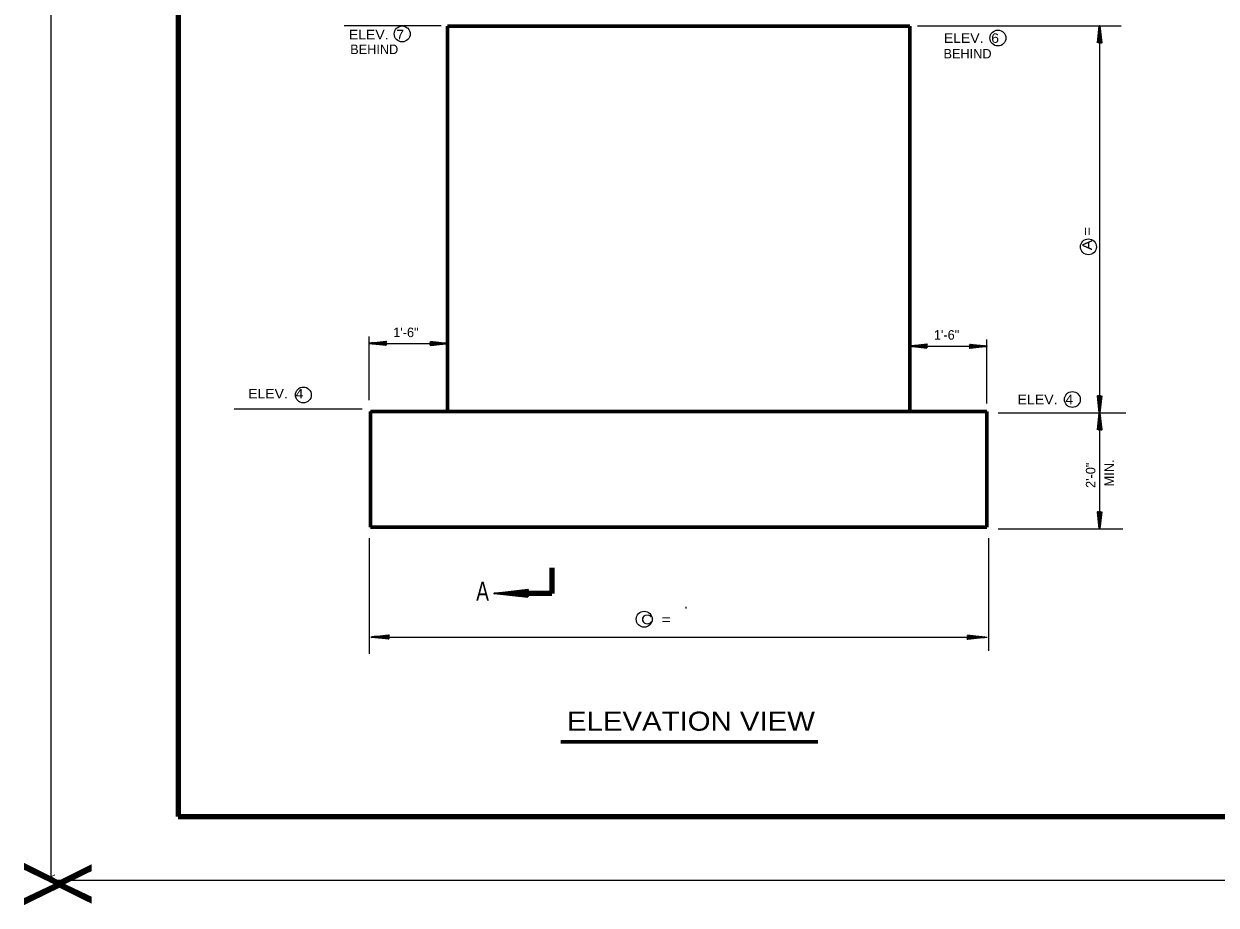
# Model space of a CAD drawing. Extents: x 1.6 to 19.9, y 2.8 to 9.5.
# Drawn here: x 16.233 to 17.696, y 7.258 to 8.339 of the extents above; entities that cross this region are included whole.
import ezdxf
from ezdxf.enums import TextEntityAlignment as Align

# ---------------------------------------------------------------- set-up
doc = ezdxf.new("R2010")
doc.units = 0
doc.header["$LTSCALE"] = 0.0047
doc.layers.add('1', color=7, linetype='Continuous', lineweight=35)
doc.layers.add('5', color=7, linetype='Continuous', lineweight=13)

msp = doc.modelspace()

# ---------------------------------------------------------------- linework, layer by layer
at = {"layer": '1', "lineweight": 25}
for p, q in [((16.26675, 9.5485), (16.26675, 7.2855)), ((16.6265, 8.33725), (16.74525, 8.33725)), ((17.329917, 8.336833), (17.5795, 8.336833)), ((17.55325, 8.3325), (17.55325, 7.719833)), ((16.65725, 7.877667), (16.65725, 7.95575)), ((16.657417, 7.94725), (16.750417, 7.94725)), ((17.321417, 7.943833), (17.414417, 7.943833)), ((17.414917, 7.87375), (17.414917, 7.951917)), ((16.491667, 7.866917), (16.648667, 7.866917)), ((17.428583, 7.862), (17.5855, 7.862)), ((17.428583, 7.719833), (17.581667, 7.719833)), ((16.65725, 7.70825), (16.65725, 7.5665)), ((17.416833, 7.70825), (17.416833, 7.570083)), ((16.659167, 7.587), (17.027, 7.587)), ((17.027, 7.587), (17.41525, 7.587)), ((17.02725, 7.587333), (17.027333, 7.587333)), ((16.26675, 7.288833), (19.894917, 7.288833))]:
    msp.add_line(p, q, dxfattribs=at)
at = {"layer": '1', "lineweight": 60}
for p, q in [((17.320417, 8.336333), (17.320417, 7.86375)), ((16.658667, 7.722), (16.658667, 7.86375)), ((17.320417, 7.86375), (17.414917, 7.86375)), ((17.414917, 7.86375), (17.414917, 7.722)), ((17.045167, 7.722), (16.658667, 7.722)), ((17.414917, 7.722), (17.045167, 7.722)), ((17.207583, 7.4585), (16.892167, 7.4585))]:
    msp.add_line(p, q, dxfattribs=at)
at = {"layer": '1'}
for p, q in [((17.551167, 8.316583), (17.55275, 8.332)), ((17.551167, 8.3165), (17.552917, 8.332)), ((17.551167, 8.3165), (17.552917, 8.332)), ((17.551417, 8.3165), (17.553, 8.331917)), ((17.5515, 8.3165), (17.55325, 8.331917)), ((17.554417, 8.316417), (17.552917, 8.33075)), ((17.553083, 8.316083), (17.553083, 8.336833)), ((17.554667, 8.3165), (17.553083, 8.330917)), ((17.554917, 8.3165), (17.553333, 8.331)), ((17.555167, 8.316583), (17.5535, 8.331)), ((16.677917, 7.94725), (16.65725, 7.94725)), ((16.677417, 7.94525), (16.662083, 7.947)), ((16.677417, 7.945333), (16.662083, 7.947)), ((16.677417, 7.945417), (16.662083, 7.947)), ((16.677583, 7.94575), (16.662167, 7.947333)), ((16.677417, 7.9455), (16.662167, 7.94725)), ((16.677417, 7.94925), (16.663083, 7.947667)), ((16.677417, 7.949083), (16.663083, 7.9475)), ((16.677583, 7.948833), (16.663167, 7.94725)), ((16.677583, 7.948583), (16.663167, 7.947)), ((16.732167, 7.94725), (16.753, 7.94725)), ((16.732417, 7.946), (16.747, 7.9475)), ((16.732583, 7.94925), (16.748083, 7.9475)), ((16.732583, 7.949167), (16.748083, 7.9475)), ((16.732583, 7.949083), (16.748083, 7.947333)), ((16.732583, 7.948833), (16.748083, 7.947167)), ((16.732583, 7.94575), (16.747, 7.94725)), ((16.732583, 7.9455), (16.747083, 7.947)), ((16.732667, 7.949333), (16.748083, 7.947583)), ((16.732667, 7.94525), (16.747083, 7.946917)), ((17.341167, 7.943833), (17.3205, 7.943833)), ((17.340833, 7.94225), (17.325417, 7.943917)), ((17.34075, 7.942), (17.325417, 7.94375)), ((17.34075, 7.941917), (17.325417, 7.943583)), ((17.34075, 7.942), (17.325417, 7.943583)), ((17.34075, 7.941833), (17.325417, 7.9435)), ((17.34075, 7.94575), (17.326417, 7.94425)), ((17.34075, 7.945667), (17.326417, 7.944083)), ((17.340833, 7.945417), (17.326417, 7.943833)), ((17.340833, 7.945167), (17.326417, 7.943583)), ((17.394, 7.943833), (17.414917, 7.943833)), ((17.394333, 7.9425), (17.408917, 7.944083)), ((17.394417, 7.94575), (17.409917, 7.944083)), ((17.394417, 7.94575), (17.409917, 7.944)), ((17.394417, 7.945667), (17.409917, 7.943917)), ((17.394417, 7.945417), (17.409917, 7.94375)), ((17.394417, 7.94225), (17.408917, 7.943833)), ((17.394417, 7.942), (17.408917, 7.943583)), ((17.3945, 7.945917), (17.409917, 7.944167)), ((17.3945, 7.941833), (17.408917, 7.9435)), ((17.551333, 7.8825), (17.552917, 7.868083)), ((17.5515, 7.8825), (17.553083, 7.868083)), ((17.55175, 7.8825), (17.553333, 7.868167)), ((17.552, 7.8825), (17.553667, 7.86825)), ((17.55325, 7.882917), (17.55325, 7.86225)), ((17.554917, 7.8825), (17.55325, 7.867167)), ((17.555083, 7.8825), (17.553333, 7.867167)), ((17.555167, 7.8825), (17.553583, 7.867)), ((17.555417, 7.8825), (17.553667, 7.867)), ((17.55525, 7.8825), (17.553667, 7.867)), ((17.551333, 7.841833), (17.552917, 7.85725)), ((17.551333, 7.84175), (17.553, 7.85725)), ((17.551417, 7.84175), (17.553083, 7.85725)), ((17.5515, 7.84175), (17.553167, 7.857167)), ((17.551667, 7.84175), (17.553417, 7.857167)), ((17.554583, 7.841667), (17.553, 7.856)), ((17.554833, 7.84175), (17.55325, 7.856083)), ((17.555083, 7.84175), (17.5535, 7.85625)), ((17.55525, 7.841833), (17.553667, 7.85625)), ((17.551333, 7.74025), (17.552917, 7.72575)), ((17.5515, 7.74025), (17.553083, 7.72575)), ((17.55175, 7.74025), (17.553333, 7.725917)), ((17.552, 7.74025), (17.553667, 7.726)), ((17.55325, 7.740667), (17.55325, 7.72)), ((17.554917, 7.74025), (17.55325, 7.724833)), ((17.555083, 7.74025), (17.553333, 7.724833)), ((17.555167, 7.74025), (17.553583, 7.72475)), ((17.555417, 7.74025), (17.553667, 7.72475)), ((17.55525, 7.74025), (17.553667, 7.72475)), ((16.851917, 7.640667), (16.8105, 7.640667)), ((16.851083, 7.636917), (16.820167, 7.640167)), ((16.851083, 7.63675), (16.820167, 7.640083)), ((16.851, 7.636583), (16.820167, 7.64)), ((16.851167, 7.6375), (16.820417, 7.64075)), ((16.851083, 7.637), (16.820417, 7.6405)), ((16.851, 7.6445), (16.82225, 7.641417)), ((16.851083, 7.644167), (16.822333, 7.641)), ((16.851167, 7.64375), (16.822417, 7.640583)), ((16.851167, 7.64325), (16.822417, 7.640083)), ((16.681333, 7.587), (16.660583, 7.587)), ((16.680833, 7.585083), (16.665417, 7.586833)), ((16.680833, 7.585167), (16.665417, 7.586833)), ((16.680833, 7.585), (16.665417, 7.58675)), ((16.680917, 7.5855), (16.6655, 7.587167)), ((16.680833, 7.58525), (16.6655, 7.587)), ((16.680833, 7.589), (16.666417, 7.5875)), ((16.680833, 7.588833), (16.666417, 7.58725)), ((16.680917, 7.588583), (16.6665, 7.587)), ((16.680917, 7.588417), (16.6665, 7.586833)), ((17.391083, 7.587), (17.411917, 7.587)), ((17.391417, 7.588917), (17.407, 7.58725)), ((17.391417, 7.588833), (17.407, 7.587167)), ((17.391417, 7.58875), (17.407, 7.587)), ((17.391417, 7.5885), (17.407, 7.586833)), ((17.391417, 7.585667), (17.405917, 7.58725)), ((17.391417, 7.585417), (17.405917, 7.587)), ((17.391417, 7.585167), (17.406, 7.58675)), ((17.3915, 7.589), (17.407, 7.58725)), ((17.3915, 7.585), (17.406, 7.586583))]:
    msp.add_line(p, q, dxfattribs=at)
at = {"layer": '1', "lineweight": 90}
for p, q in [((16.881333, 7.672), (16.881333, 7.640583)), ((16.881333, 7.640583), (16.849667, 7.640583))]:
    msp.add_line(p, q, dxfattribs=at)
at = {"layer": '1', "lineweight": 13}
msp.add_line((17.045417, 7.624167), (17.045417, 7.622167), dxfattribs=at)
at = {"layer": '1', "lineweight": 106}
msp.add_line((16.423, 7.367), (19.823, 7.367), dxfattribs=at)
msp.add_lwpolyline([(19.823, 7.367), (19.823, 9.467), (16.423, 9.467), (16.423, 7.367)], dxfattribs=at)
at = {"layer": '1', "lineweight": 60}
for points in [[(16.658667, 7.86375), (16.753167, 7.86375), (16.753167, 8.336417)], [(16.753167, 8.336417), (17.052167, 8.336417), (17.320417, 8.336417)], [(16.753167, 7.86375), (17.044917, 7.86375), (17.320417, 7.86375)]]:
    msp.add_lwpolyline(points, dxfattribs=at)
at = {"layer": '1'}
for points in [[(17.550833, 8.316083), (17.553083, 8.336833), (17.555417, 8.316083), (17.553083, 8.31725)], [(16.677917, 7.945), (16.65725, 7.94725), (16.677917, 7.949667), (16.676833, 7.94725)], [(16.732167, 7.9495), (16.753, 7.94725), (16.732167, 7.945), (16.73325, 7.94725)], [(17.341167, 7.941583), (17.3205, 7.943833), (17.341167, 7.94625), (17.340167, 7.943833)], [(17.394, 7.946083), (17.414917, 7.943833), (17.394, 7.9415), (17.395167, 7.943833)], [(17.555583, 7.882917), (17.55325, 7.86225), (17.551, 7.882917), (17.553333, 7.881833)], [(17.553667, 7.8815), (17.553667, 7.87225), (17.553417, 7.872333), (17.553667, 7.874083)], [(17.551, 7.841333), (17.55325, 7.862), (17.555583, 7.841333), (17.55325, 7.8425)], [(17.555583, 7.740667), (17.55325, 7.72), (17.551, 7.740667), (17.553333, 7.7395)], [(17.553667, 7.73925), (17.553667, 7.73), (17.553417, 7.730083), (17.553667, 7.731833)], [(16.851917, 7.636), (16.8105, 7.640667), (16.851917, 7.64525), (16.84975, 7.640583)], [(16.681333, 7.58475), (16.660583, 7.587), (16.681333, 7.589417), (16.680167, 7.587)], [(17.391083, 7.58925), (17.411917, 7.587), (17.391083, 7.584667), (17.392167, 7.587)]]:
    msp.add_lwpolyline(points, close=True, dxfattribs=at)
for points in [[(17.552917, 8.3175), (17.552667, 8.32675), (17.553, 8.326667), (17.552917, 8.325), (17.552667, 8.3175), (17.552583, 8.3235), (17.552417, 8.31725), (17.552333, 8.321583), (17.552083, 8.317), (17.552583, 8.324167), (17.553, 8.333417), (17.5535, 8.331417), (17.55325, 8.334), (17.553333, 8.3175), (17.553667, 8.322333), (17.553667, 8.31725), (17.552917, 8.327833), (17.554, 8.317167), (17.552917, 8.317583), (17.551417, 8.316667), (17.55175, 8.317167), (17.552583, 8.317583), (17.552417, 8.318083), (17.551667, 8.31775), (17.553167, 8.3175), (17.554, 8.317), (17.555083, 8.316583)], [(16.669917, 7.94675), (16.660667, 7.947167), (16.662583, 7.947667), (16.660083, 7.9475), (16.6765, 7.9475), (16.671667, 7.947833), (16.67675, 7.947833), (16.666167, 7.947), (16.676833, 7.94825), (16.676417, 7.947), (16.677333, 7.945667)], [(16.6765, 7.947), (16.667333, 7.946917), (16.667333, 7.947167), (16.669167, 7.947), (16.6765, 7.946917)], [(16.6765, 7.946917), (16.670583, 7.94675), (16.67675, 7.946583), (16.672417, 7.946417), (16.676917, 7.94625), (16.669917, 7.94675)], [(16.677333, 7.945667), (16.676833, 7.946), (16.676417, 7.94675), (16.675917, 7.9465), (16.676333, 7.945917)], [(16.676333, 7.945917), (16.676667, 7.947333), (16.677, 7.94825), (16.677417, 7.94925)], [(16.733583, 7.9475), (16.742917, 7.947667), (16.74275, 7.9475), (16.741083, 7.9475), (16.733583, 7.947667), (16.739583, 7.947833), (16.733333, 7.948), (16.737667, 7.948167), (16.733083, 7.948417), (16.74025, 7.947833), (16.7495, 7.9475), (16.747667, 7.946917), (16.750167, 7.947167), (16.733583, 7.947), (16.738417, 7.94675), (16.733333, 7.94675), (16.743917, 7.9475), (16.733167, 7.946333), (16.733667, 7.9475), (16.732667, 7.948917), (16.733167, 7.948583), (16.733667, 7.947833), (16.734167, 7.948083), (16.733667, 7.94875), (16.733417, 7.94725), (16.733, 7.946333), (16.732667, 7.945333)], [(17.339833, 7.943583), (17.330583, 7.9435), (17.330583, 7.94375), (17.332417, 7.943583), (17.339833, 7.9435), (17.333917, 7.94325), (17.340083, 7.943167), (17.335667, 7.943), (17.340167, 7.94275), (17.333167, 7.94325), (17.323917, 7.94375), (17.325833, 7.94425), (17.323333, 7.944), (17.339833, 7.944083), (17.334917, 7.944417), (17.340083, 7.944417), (17.3295, 7.943583), (17.340167, 7.94475), (17.33975, 7.943583), (17.340583, 7.94225), (17.340167, 7.9425), (17.33975, 7.94325), (17.339167, 7.943083), (17.339583, 7.9425), (17.339917, 7.943917), (17.34025, 7.94475), (17.34075, 7.94575)], [(17.395417, 7.944083), (17.40475, 7.94425), (17.404667, 7.944), (17.402917, 7.944083), (17.395417, 7.94425), (17.401417, 7.944417), (17.395167, 7.9445), (17.3995, 7.94475), (17.394917, 7.945), (17.402167, 7.944417), (17.411417, 7.944), (17.4095, 7.9435), (17.412083, 7.94375), (17.395417, 7.943583), (17.40025, 7.94325), (17.395167, 7.94325), (17.40575, 7.944), (17.395083, 7.942917), (17.3955, 7.944), (17.394583, 7.9455), (17.395083, 7.945167), (17.3955, 7.944417), (17.396, 7.944667), (17.395583, 7.94525), (17.39525, 7.94375), (17.394917, 7.942917), (17.3945, 7.941917)], [(17.553667, 7.8815), (17.553917, 7.875583), (17.553917, 7.881833), (17.554167, 7.8775), (17.554333, 7.882), (17.553917, 7.874833), (17.553417, 7.865667), (17.552917, 7.867583), (17.553167, 7.865), (17.553083, 7.8815), (17.55275, 7.87675), (17.55275, 7.881833), (17.553583, 7.87125), (17.552333, 7.881917), (17.553583, 7.881417), (17.554917, 7.882333), (17.554667, 7.881917), (17.553917, 7.881417), (17.554, 7.881), (17.55475, 7.88125), (17.55325, 7.881583), (17.552333, 7.882), (17.551417, 7.8825)], [(17.553, 7.84275), (17.552917, 7.852), (17.553167, 7.851917), (17.553, 7.850167), (17.552917, 7.84275), (17.552667, 7.84875), (17.552583, 7.8425), (17.552417, 7.846833), (17.55225, 7.84225), (17.552667, 7.849417), (17.553167, 7.858583), (17.553667, 7.856667), (17.553417, 7.85925), (17.5535, 7.84275), (17.553833, 7.847583), (17.553833, 7.8425), (17.553083, 7.853083), (17.554167, 7.842333), (17.553083, 7.842833), (17.551667, 7.841917), (17.551917, 7.842333), (17.552667, 7.842833), (17.552583, 7.84325), (17.551833, 7.843), (17.553333, 7.842667), (17.554167, 7.84225), (17.555167, 7.841833)], [(17.553667, 7.73925), (17.553917, 7.73325), (17.553917, 7.7395), (17.554167, 7.735167), (17.554333, 7.73975), (17.553917, 7.732583), (17.553417, 7.723417), (17.552917, 7.725333), (17.553167, 7.72275), (17.553083, 7.73925), (17.55275, 7.7345), (17.55275, 7.7395), (17.553583, 7.728917), (17.552333, 7.739667), (17.553583, 7.739167), (17.554917, 7.740083), (17.554667, 7.739667), (17.553917, 7.739167), (17.554, 7.73875), (17.55475, 7.739), (17.55325, 7.739333), (17.552333, 7.73975), (17.551417, 7.74025)], [(16.849167, 7.640083), (16.830667, 7.639833), (16.83075, 7.640333), (16.834333, 7.640083), (16.849167, 7.639833), (16.83725, 7.6395), (16.849667, 7.63925), (16.840917, 7.638917), (16.849917, 7.6385), (16.835833, 7.6395), (16.817417, 7.640333), (16.821167, 7.641333), (16.816167, 7.640917), (16.849167, 7.641), (16.8395, 7.641667), (16.849667, 7.641667), (16.828583, 7.640167), (16.849833, 7.6425), (16.849, 7.640167), (16.85075, 7.63725), (16.849833, 7.637917), (16.849, 7.6395), (16.847917, 7.639083), (16.848667, 7.63775), (16.84925, 7.64075), (16.850167, 7.6425), (16.851, 7.6445)], [(16.679917, 7.586833), (16.670667, 7.586667), (16.670667, 7.586917), (16.672417, 7.586833), (16.679917, 7.586667), (16.673917, 7.5865), (16.680167, 7.586333), (16.67575, 7.58625), (16.68025, 7.586), (16.67325, 7.5865), (16.664, 7.586917), (16.665917, 7.5875), (16.663417, 7.58725), (16.679917, 7.58725), (16.675083, 7.587583), (16.680167, 7.587583), (16.669583, 7.586833), (16.680167, 7.588), (16.679833, 7.586833), (16.680667, 7.585417), (16.680167, 7.58575), (16.679833, 7.5865), (16.67925, 7.58625), (16.679667, 7.585667), (16.679917, 7.587167), (16.680417, 7.588), (16.680833, 7.589)], [(17.392417, 7.58725), (17.40175, 7.587333), (17.401667, 7.587167), (17.399917, 7.58725), (17.392417, 7.587333), (17.3985, 7.5875), (17.39225, 7.587667), (17.3965, 7.587833), (17.392, 7.588083), (17.399167, 7.5875), (17.408417, 7.587167), (17.4065, 7.586583), (17.409167, 7.586833), (17.392417, 7.58675), (17.397333, 7.586417), (17.39225, 7.586417), (17.40275, 7.587167), (17.392083, 7.586), (17.392583, 7.587167), (17.391667, 7.588583), (17.392083, 7.58825), (17.392583, 7.5875), (17.393, 7.58775), (17.392667, 7.588417), (17.392333, 7.586917), (17.391917, 7.586), (17.3915, 7.585)]]:
    msp.add_lwpolyline(points, dxfattribs=at)
at = {"layer": '1', "lineweight": 40}
msp.add_lwpolyline([(16.423, 7.367), (19.148, 7.367), (19.148, 7.742), (19.823, 7.742)], dxfattribs=at)
at = {"layer": '1', "lineweight": 13}
for centre in [(16.697648, 8.326939), (17.42843, 8.321939), (17.539504, 8.065747), (16.576398, 7.884048), (17.519758, 7.878501), (16.994523, 7.608892)]:
    msp.add_circle(centre, 0.009766, dxfattribs=at)

# ---------------------------------------------------------------- texts
at = {"layer": '1'}
for p in [(16.686667, 7.955), (17.349917, 7.951917)]:
    msp.add_text('1\'-6"', height=0.01167, dxfattribs=at).set_placement(p)
msp.add_text('2\'-0"', height=0.01167, rotation=90, dxfattribs=at).set_placement((17.548, 7.77))
for s, width, p in [('A', 0.75, (16.788417, 7.631583)), ('ELEVATION VIEW', 1.15, (16.89975, 7.472167))]:
    msp.add_text(s, height=0.02342, dxfattribs=dict(at, width=width)).set_placement(p)
at = {"layer": '1', "width": 0.75}
for height, p in [(0.08333, (16.2335, 7.284292)), (0.01033, (16.261583, 7.293))]:
    msp.add_text('X', height=height, rotation=270, dxfattribs=at).set_placement(p, align=Align.CENTER)
at = {"layer": '5'}
for s, height, width, p in [('ELEV.  7', 0.01167, 1.1, (16.63225, 8.320333)), ('ELEV.  6', 0.01167, 1.1, (17.362083, 8.316)), ('ELEV.  4', 0.01167, 1.1, (16.508667, 7.87975)), ('ELEV.  4', 0.01175, 1.1, (17.452583, 7.872667)), ('C  =      ', 0.01167, 1.25, (16.99075, 7.602833))]:
    msp.add_text(s, height=height, dxfattribs=dict(at, width=width)).set_placement(p)
for p in [(16.633833, 8.30225), (17.361667, 8.296833)]:
    msp.add_text('BEHIND', height=0.01167, dxfattribs=at).set_placement(p)
at = {"layer": '5', "width": 1.2}
msp.add_text('A =      ', height=0.01175, rotation=90, dxfattribs=at).set_placement((17.543833, 8.061583))
at = {"layer": '5'}
msp.add_text('MIN.', height=0.01175, rotation=90, dxfattribs=at).set_placement((17.57075, 7.771833))

doc.saveas('drawing.dxf')
